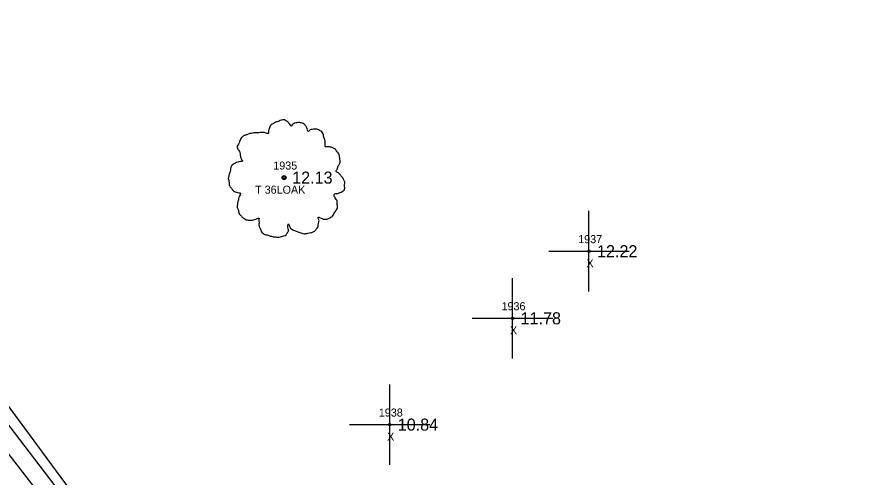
# Model space of a CAD drawing. Extents: x 2042211 to 2045853, y 303080 to 309569.
# Drawn here: x 2044074.2 to 2044179.7, y 305225.7 to 305282.9 of the extents above; entities that cross this region are included whole.
import ezdxf

# ---------------------------------------------------------------- set-up
doc = ezdxf.new("R2010")
doc.units = 0
for name, color, linetype in [('BR_500YR_SCOUR', 7, 'Continuous'), ('RD_EX_H2O', 7, 'Continuous'), ('RD_EX_Misc', 7, 'Continuous'), ('RD_EX_Misc_txCode', 7, 'Continuous'), ('RD_EX_TX_Misc_ELEV', 7, 'Continuous'), ('RD_EX_TX_VEG_ELEV', 7, 'Continuous'), ('RD_EX_VEG_txCode', 7, 'Continuous'), ('RD_SMD_Locator', 7, 'Continuous')]:
    doc.layers.add(name, color=color, linetype=linetype)

msp = doc.modelspace()

# ---------------------------------------------------------------- linework, layer by layer
at = {"layer": 'BR_500YR_SCOUR'}
for centre, radius in [((2044107.4, 305262.91), 0.25), ((2044107.4, 305262.91), 0.15), ((2044107.39, 305262.89), 0.0001)]:
    msp.add_circle(centre, radius, dxfattribs=at)
for points in [[(2044107.53, 305270.08), (2044107.23, 305270.1), (2044106.91, 305270), (2044106.66, 305269.9), (2044106.43, 305269.83), (2044106.21, 305269.73), (2044105.91, 305269.55), (2044105.68, 305269.35), (2044105.56, 305269.1), (2044105.51, 305268.88), (2044105.46, 305268.6), (2044105.46, 305268.43), (2044105.33, 305268.4), (2044105.18, 305268.43), (2044104.93, 305268.5), (2044104.68, 305268.5), (2044104.43, 305268.5), (2044104.08, 305268.48), (2044103.73, 305268.48), (2044103.46, 305268.43), (2044103.13, 305268.38), (2044102.76, 305268.25), (2044102.41, 305268.13), (2044102.11, 305267.88), (2044101.86, 305267.4), (2044101.73, 305267.05), (2044101.58, 305266.8), (2044101.73, 305266.35), (2044101.91, 305266), (2044101.93, 305265.8), (2044102.01, 305265.38), (2044102.11, 305265.16), (2044102.23, 305264.96), (2044102.16, 305264.93), (2044101.78, 305264.88), (2044101.48, 305264.78), (2044101.06, 305264.56), (2044100.83, 305264.33), (2044100.73, 305264.01), (2044100.71, 305263.66), (2044100.61, 305263.46), (2044100.53, 305263.18), (2044100.51, 305263.11), (2044100.46, 305262.78), (2044100.56, 305262.33), (2044100.58, 305261.98), (2044100.71, 305261.76), (2044100.86, 305261.58), (2044101.03, 305261.33), (2044101.43, 305261.11), (2044101.76, 305261.01), (2044101.96, 305260.98), (2044101.78, 305260.48), (2044101.73, 305260.13), (2044101.61, 305259.73), (2044101.61, 305259.66), (2044101.56, 305259.18), (2044101.71, 305258.86), (2044101.78, 305258.48), (2044101.96, 305258.26), (2044102.23, 305257.96), (2044102.56, 305257.73), (2044103.06, 305257.61), (2044103.46, 305257.63), (2044104.03, 305257.81), (2044104.28, 305257.88), (2044104.26, 305257.71), (2044104.28, 305257.33), (2044104.28, 305256.91), (2044104.43, 305256.58), (2044104.53, 305256.31), (2044104.68, 305256.06), (2044105.01, 305255.83), (2044105.41, 305255.76), (2044105.83, 305255.61), (2044106.28, 305255.53), (2044106.78, 305255.51), (2044107.38, 305255.66), (2044107.65, 305255.78), (2044107.75, 305255.96), (2044107.95, 305256.33), (2044107.9, 305256.56), (2044107.93, 305257.16), (2044108.03, 305256.98), (2044108.2, 305256.63), (2044108.7, 305256.33), (2044109.1, 305256.16), (2044109.58, 305256.01), (2044109.88, 305255.93), (2044110.35, 305256.01), (2044110.73, 305256.08), (2044111.1, 305256.21), (2044111.4, 305256.48), (2044111.58, 305256.76), (2044111.63, 305257.03), (2044111.7, 305257.41), (2044111.75, 305257.58)], [(2044111.75, 305257.58), (2044111.68, 305257.76), (2044111.63, 305258.01), (2044111.7, 305257.98), (2044111.88, 305257.93), (2044112.15, 305257.81), (2044112.38, 305257.73), (2044112.7, 305257.76), (2044112.98, 305257.86), (2044113.43, 305258.13), (2044113.7, 305258.61), (2044113.98, 305259.01), (2044114.05, 305259.33), (2044114, 305259.56), (2044113.98, 305260.06), (2044113.78, 305260.31), (2044113.73, 305260.43), (2044113.63, 305260.83), (2044113.7, 305260.88), (2044113.98, 305260.93), (2044114.35, 305261.06), (2044114.63, 305261.18), (2044114.85, 305261.36), (2044114.93, 305261.58), (2044114.9, 305261.98), (2044114.95, 305262.38), (2044114.88, 305262.53), (2044114.78, 305262.68), (2044114.7, 305262.88), (2044114.55, 305263.03), (2044114.45, 305263.18), (2044114.35, 305263.28), (2044114.23, 305263.43), (2044114.05, 305263.56), (2044113.9, 305263.61), (2044113.85, 305263.76), (2044114, 305263.96), (2044114.05, 305264.06), (2044114.08, 305264.28), (2044114.3, 305264.63), (2044114.35, 305265.03), (2044114.3, 305265.46), (2044114.25, 305265.73), (2044114.1, 305266), (2044113.9, 305266.25), (2044113.78, 305266.43), (2044113.6, 305266.55), (2044113.28, 305266.68), (2044113.03, 305266.73), (2044112.68, 305266.73), (2044112.48, 305266.78), (2044112.5, 305266.83), (2044112.5, 305266.98), (2044112.5, 305267.25), (2044112.43, 305267.7), (2044112.28, 305268.2), (2044112.28, 305268.23), (2044112.18, 305268.48), (2044111.95, 305268.68), (2044111.78, 305268.78), (2044111.58, 305268.9), (2044111.33, 305268.93), (2044111.03, 305268.93), (2044110.75, 305268.88), (2044110.55, 305268.78), (2044110.38, 305268.65), (2044110.3, 305268.8), (2044110.2, 305269.1), (2044110.15, 305269.25), (2044110, 305269.43), (2044109.78, 305269.63), (2044109.33, 305269.75), (2044108.7, 305269.68), (2044108.4, 305269.48), (2044108.25, 305269.3), (2044108.2, 305269.43), (2044108, 305269.63), (2044107.9, 305269.8), (2044107.73, 305269.93), (2044107.58, 305270.03), (2044107.48, 305270.08)]]:
    msp.add_spline(points, degree=3, dxfattribs=at)
at = {"layer": 'RD_EX_H2O'}
for points in [[(2043695.41, 305785.95), (2043753.23, 305702.74), (2043816.84, 305621.67), (2043878.98, 305542.47), (2043936.42, 305466.41), (2044001.08, 305383.06), (2044036.64, 305336.24), (2044042.32, 305312.25), (2044044.08, 305296.68), (2044037.04, 305284.58), (2044037.23, 305281.89), (2044040.11, 305279.62), (2044044.74, 305276.06), (2044050.89, 305261.28), (2044092.5, 305206.78), (2044153.45, 305129.2), (2044155.72, 305128.46), (2044158.75, 305129.8), (2044171.64, 305145.93), (2044183.17, 305157.87), (2044199.16, 305188.17), (2044208.66, 305215.31)], [(2044033.22, 305275.98), (2044035.9, 305278.5), (2044040.04, 305277.28), (2044042.29, 305273.95), (2044048.6, 305260.29), (2044090.99, 305205.39), (2044151.22, 305127.18), (2044154.78, 305124.28), (2044202.92, 305070.22), (2044216.63, 305053.71), (2044279.58, 304974.12), (2044337.99, 304907.57), (2044344.68, 304901.99)], [(2044052.64, 305262.28), (2044093.07, 305207.37), (2044155.92, 305130.37), (2044157.38, 305130.75), (2044170.33, 305147.63), (2044181.38, 305159.73), (2044197.15, 305188.95), (2044208.08, 305219.28), (2044210.72, 305219.24), (2044215.12, 305217.08), (2044202.83, 305184.83), (2044185.43, 305151.79), (2044169.6, 305138.4), (2044160.58, 305125.38), (2044211.54, 305068.64), (2044219.9, 305056.44), (2044285.19, 304978.84), (2044339.94, 304911.4), (2044347.53, 304904.82), (2044347.6, 304901.86)]]:
    msp.add_lwpolyline(points, dxfattribs=at)
at = {"layer": 'RD_EX_Misc'}
for p, q in [((2044145.29, 305248.76), (2044145.29, 305258.76)), ((2044140.29, 305253.76), (2044150.29, 305253.76)), ((2044135.79, 305240.42), (2044135.79, 305250.42)), ((2044130.79, 305245.42), (2044140.79, 305245.42)), ((2044120.52, 305227.2), (2044120.52, 305237.2)), ((2044115.52, 305232.2), (2044125.52, 305232.2))]:
    msp.add_line(p, q, dxfattribs=at)
at = {"layer": 'RD_SMD_Locator'}
for centre in [(2044145.29, 305253.76), (2044135.79, 305245.42), (2044120.52, 305232.2)]:
    msp.add_circle(centre, 0.15, dxfattribs=at)

# ---------------------------------------------------------------- texts
at = {"layer": 'RD_EX_Misc_txCode'}
for s, p in [('1937', (2044143.95, 305254.76)), ('X', (2044144.98, 305251.76)), ('1936', (2044134.42, 305246.42)), ('X', (2044135.47, 305243.42)), ('1938', (2044119.17, 305233.2)), ('X', (2044120.2, 305230.2))]:
    msp.add_text(s, height=1, dxfattribs=at).set_placement(p)
at = {"layer": 'RD_EX_TX_Misc_ELEV'}
for s, p in [('12.22', (2044146.29, 305253.01)), ('11.78', (2044136.79, 305244.67)), ('10.84', (2044121.52, 305231.45))]:
    msp.add_text(s, height=1.5, dxfattribs=at).set_placement(p)
at = {"layer": 'RD_EX_TX_VEG_ELEV'}
msp.add_text('12.13', height=1.5, dxfattribs=at).set_placement((2044108.4, 305262.16))
at = {"layer": 'RD_EX_VEG_txCode'}
for s, p in [('1935', (2044106.05, 305263.91)), ('T 36LOAK', (2044103.79, 305260.91))]:
    msp.add_text(s, height=1, dxfattribs=at).set_placement(p)

doc.saveas('drawing.dxf')
